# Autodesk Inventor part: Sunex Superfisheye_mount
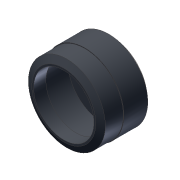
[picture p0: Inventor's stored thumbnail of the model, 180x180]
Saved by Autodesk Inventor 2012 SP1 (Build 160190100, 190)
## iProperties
Created: 2012-03
Part Number: Sunex Superfisheye_mount
Material: Aluminum-6061
Document SubType Name: Modeling
Designer: jdh
Density: 2.71 g/cm^3
Mass: 90.7455 g
Surface Area: 212.886 cm^2
Volume: 33.4854 cm^3
Author: jdh
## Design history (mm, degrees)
sketch "Sketch1"
  geometry: L1 (0, 0)-(0, 43.51); L2 (0, 0)-(33.715, 0); L3 (0, 43.51)-(33.715, 43.51); L4 (25.019, 33.35)-(25.019, 43.51); L5 (31.928, 40.97)-(31.928, 26.06); L6 (25.019, 33.35)-(29.845, 33.35); L7 (29.845, 33.35)-(29.845, 10.49); L8 (29.845, 10.49)-(21.831, 10.49); L9 (25.019, 43.51)-(26.543, 43.51); L10 (31.928, 40.97)-(26.543, 43.51); L11 (20.561, 7.95)-(20.561, 0); L12 (21.755, 3.924)-(21.755, 0); L13 (20.561, 0)-(21.755, 0); L14 (21.755, 3.924)-(23.451, 3.924); L15 (23.451, 3.924)-(23.451, 4.826); L16 (23.451, 4.826)-(28.575, 4.826); L17 (28.575, 4.826)-(28.575, 3.962); L18 (28.575, 3.962)-(29.718, 3.962); L19 (29.718, 3.962)-(29.718, 6.248); L20 (29.718, 6.248)-(32.487, 6.248); L21 (32.487, 6.248)-(32.487, 26.06); L22 (32.487, 26.06)-(31.928, 26.06); L23 (21.831, 10.49)-(21.831, 7.95); L24 (21.831, 7.95)-(20.561, 7.95); L25 (29.718, 6.248)-(21.831, 6.248); L26 (21.831, 6.248)-(21.831, 7.95)
  constraints: 52 end point, 16 perpendicular, 6 parallel, 4 point on line, 1 collinear, 1 vertical
  dimensions: "d0" = 43.5102 distance of L1.start L1.end; "d1" = 10.16 distance of L4.start L4.end; "d2" = 2.54 distance from line of L5.start L3; "d3" = 50.038 diameter of L4 L1; "d4" = 63.8556 diameter of L5 L1; "d5" = 14.9098 distance of L5.start L5.end; "d6" = 4.826 distance between parallel lines of L7 L4; "d7" = 1.524 distance of L4.end L9.end; "d8" = 33.02 distance between parallel lines of L8 L3; "d9" = 41.1226 diameter of L11 L1; "d10" = 1.1938 distance between parallel lines of L11 L12; "d11" = 3.9243 distance of L12.start L12.end; "d12" = 46.9011 diameter of L15 L1; "d13" = 4.826 distance between parallel lines of L2 L16; "d14" = 57.15 diameter of L17 L1; "d15" = 59.436 diameter of L19 L1; "d16" = 2.286 distance of L18.end L19.end; "d17" = 64.9732 diameter of L21 L1; "d18" = 35.56 distance between parallel lines of L3 L24; "d19" = 1.27 distance between parallel lines of L11 L23; "d20" = 3.9624 distance between parallel lines of L2 L18
revolve "Revolution1" stored, may be unused: angle "d21" = 90 deg
revolve "Revolution2" stored, may be unused: angle "d22" = 90 deg
body "Solid1"
